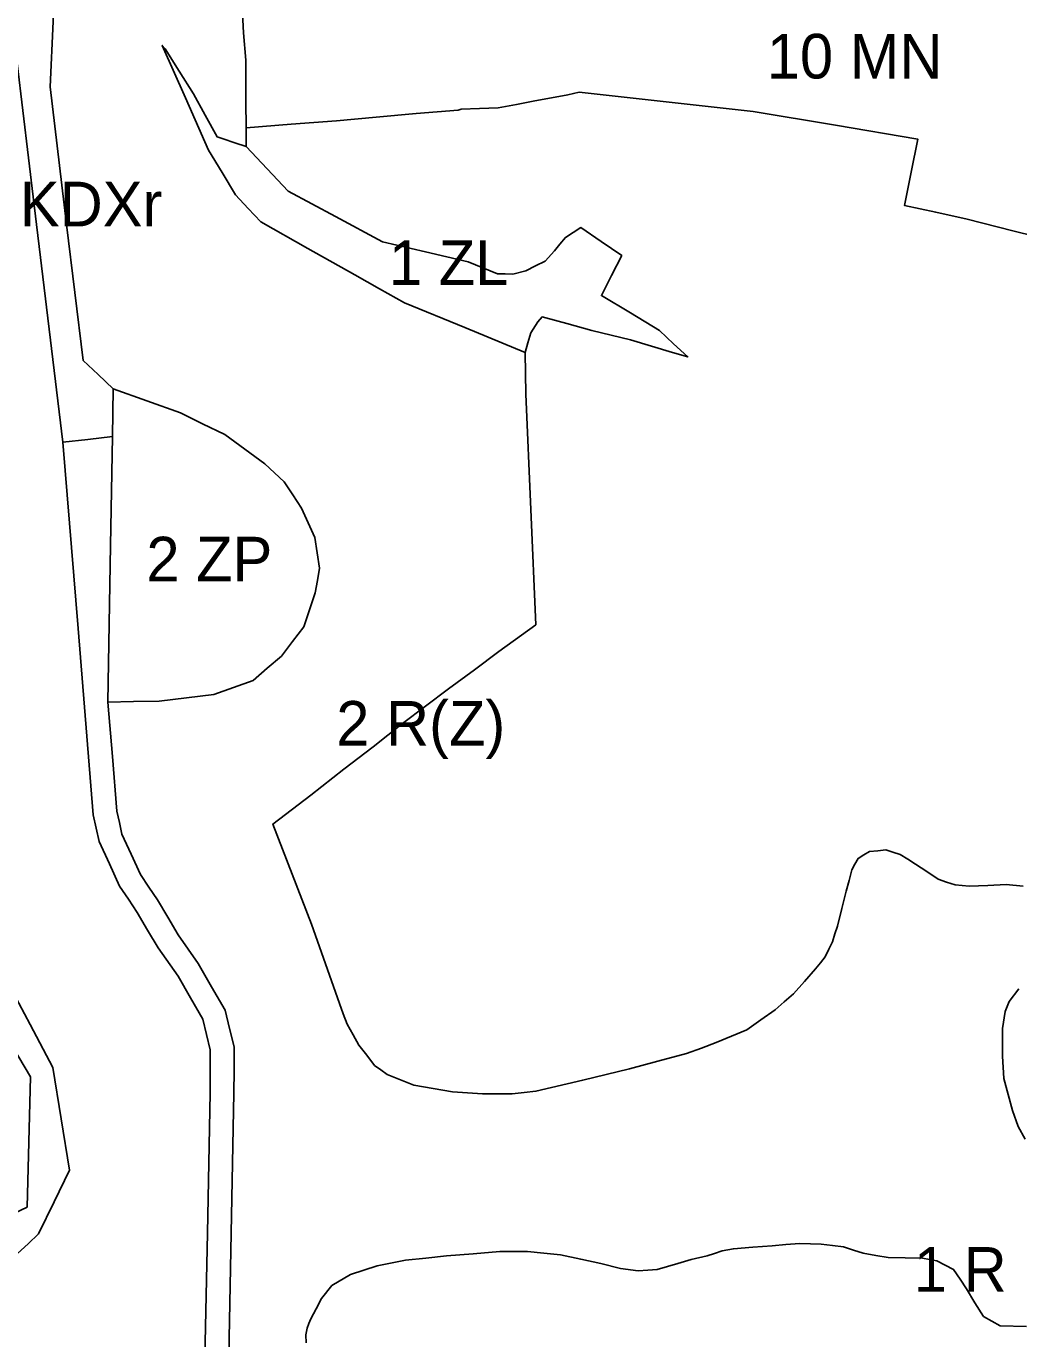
# Model space of a CAD drawing. Extents: x -295551 to -293631, y 22633 to 24461.
# Drawn here: x -294907.1 to -294573.4, y 23168.5 to 23609.6 of the extents above; entities that cross this region are included whole.
import ezdxf

# ---------------------------------------------------------------- set-up
doc = ezdxf.new("R2010")
doc.units = 0
doc.layers.add('linie_rozgraniczajace', color=7, linetype='Continuous')
doc.layers.add('oznaczenia_przeznaczen', color=7, linetype='Continuous')

msp = doc.modelspace()

# ---------------------------------------------------------------- linework, layer by layer
at = {"layer": 'linie_rozgraniczajace'}
for points in [[(-294833.26, 23584.36), (-294833.285, 23591.3), (-294833.31, 23598.24), (-294834, 23607.44), (-294834.32, 23611.79), (-294835.076, 23621.65), (-294835.832, 23631.51), (-294836.521, 23637.03), (-294837.21, 23642.55), (-294838.325, 23651.48), (-294839.44, 23660.41), (-294840.989, 23667.771)], [(-294914.016, 23629.187), (-294904.383, 23549.544), (-294894.749, 23469.901), (-294889.66, 23407.262), (-294884.572, 23344.624), (-294883.566, 23340.113), (-294882.561, 23335.602), (-294879.136, 23328.127), (-294875.71, 23320.651), (-294872.746, 23316.233), (-294869.781, 23311.815), (-294866.279, 23305.886), (-294862.778, 23299.956), (-294856.04, 23290.395), (-294851.888, 23283.151), (-294847.736, 23275.907), (-294846.469, 23270.782), (-294845.202, 23265.658), (-294845.232, 23258.409), (-294845.262, 23251.16), (-294846.188, 23203.99), (-294847.114, 23156.82)], [(-294899.096, 23589.295), (-294898.065, 23611.273)], [(-294834.32, 23611.79), (-294834, 23607.44), (-294833.31, 23598.24), (-294833.285, 23591.3), (-294833.26, 23584.36), (-294833.12, 23575.47), (-294833.15, 23569.21), (-294837, 23570.503), (-294840.849, 23571.796), (-294842.915, 23572.5), (-294846.898, 23579.745), (-294850.88, 23586.99), (-294855.658, 23594.502), (-294860.436, 23602.014), (-294861.352, 23603.227), (-294853.586, 23585.608), (-294845.82, 23567.99), (-294841.27, 23560.47), (-294836.72, 23552.95), (-294832.445, 23548.43), (-294828.17, 23543.91), (-294812.375, 23534.994), (-294796.58, 23526.077), (-294788.265, 23521.384), (-294779.95, 23516.69), (-294759.64, 23508.345), (-294739.33, 23500), (-294739.165, 23486.02), (-294737.448, 23447.26), (-294735.73, 23408.5), (-294740.576, 23404.966), (-294748.14, 23399.45), (-294756.39, 23393.32), (-294765.085, 23386.945), (-294780.59, 23375.36), (-294790.43, 23367.52), (-294800.26, 23359.99), (-294811.42, 23351.2), (-294824.153, 23341.524), (-294817.686, 23324.669), (-294811.218, 23307.814), (-294806.515, 23294.519), (-294801.812, 23281.223), (-294800.525, 23277.727), (-294799.238, 23274.231), (-294797.228, 23270.695), (-294795.217, 23267.159), (-294792.604, 23263.784), (-294789.99, 23260.408), (-294787.858, 23258.881), (-294785.727, 23257.354), (-294781.272, 23255.569), (-294776.817, 23253.784), (-294770.274, 23252.625), (-294763.731, 23251.466), (-294758.721, 23251.135), (-294753.711, 23250.804), (-294748.7, 23250.846), (-294743.69, 23250.887), (-294739.703, 23251.296), (-294735.717, 23251.704), (-294720.001, 23255.454), (-294704.284, 23259.203), (-294694.675, 23261.823), (-294685.067, 23264.444), (-294680.073, 23266.243), (-294675.079, 23268.042), (-294669.941, 23270.218), (-294664.803, 23272.395), (-294660.064, 23275.755), (-294655.324, 23279.114), (-294652.237, 23281.758), (-294649.15, 23284.402), (-294645.406, 23288.615), (-294641.662, 23292.829), (-294640.067, 23294.876), (-294638.471, 23296.923), (-294637.242, 23299.437), (-294636.013, 23301.951), (-294635.165, 23304.595), (-294634.317, 23307.239), (-294632.845, 23313.099), (-294631.373, 23318.959)], [(-294839.111, 23156.928), (-294838.187, 23203.997), (-294837.262, 23251.065), (-294837.23, 23258.84), (-294837.198, 23266.616), (-294838.718, 23272.765), (-294840.238, 23278.913), (-294844.762, 23286.806), (-294849.285, 23294.698), (-294852.669, 23299.5), (-294856.053, 23304.301), (-294859.531, 23310.191), (-294863.009, 23316.081), (-294865.858, 23320.326), (-294868.707, 23324.572), (-294871.822, 23331.369), (-294874.936, 23338.167), (-294875.79, 23341.995), (-294876.643, 23345.823), (-294878.133, 23364.17), (-294879.624, 23382.516), (-294871.006, 23382.646), (-294862.389, 23382.776), (-294853.199, 23383.905), (-294844.008, 23385.034), (-294837.382, 23387.419), (-294830.756, 23389.805), (-294826.039, 23393.865), (-294821.322, 23397.926), (-294817.546, 23402.874), (-294813.77, 23407.822), (-294811.845, 23413.517), (-294809.92, 23419.212), (-294809.187, 23423.373), (-294808.453, 23427.534), (-294809.27, 23432.687), (-294810.087, 23437.841), (-294812.297, 23442.757), (-294814.507, 23447.674), (-294817.417, 23452.106), (-294820.327, 23456.538), (-294826.928, 23462.541), (-294833.64, 23467.464), (-294840.352, 23472.386), (-294847.796, 23476.074), (-294855.241, 23479.762), (-294866.559, 23483.766), (-294877.877, 23487.769), (-294882.936, 23492.55), (-294887.994, 23497.331), (-294893.517, 23542.987), (-294899.096, 23589.295)], [(-294559.94, 23537.03), (-294575.31, 23540.915), (-294590.68, 23544.8), (-294601.256, 23547.111), (-294611.831, 23549.422), (-294609.576, 23560.586), (-294607.32, 23571.75), (-294635.005, 23576.375), (-294662.69, 23581), (-294691.91, 23584.275), (-294721.13, 23587.55), (-294725.01, 23586.62), (-294730.53, 23585.575), (-294736.05, 23584.53), (-294742.245, 23583.355), (-294748.44, 23582.18), (-294754.64, 23581.97), (-294760.84, 23581.76), (-294761.82, 23581.44), (-294768.93, 23580.9), (-294776.04, 23580.36), (-294789.43, 23579.13), (-294802.82, 23577.9), (-294817.97, 23576.685), (-294833.12, 23575.47), (-294833.26, 23584.36)], [(-294733.64, 23511.968), (-294732.371, 23511.622), (-294725.301, 23509.696), (-294716.963, 23507.423), (-294710.462, 23505.843), (-294703.962, 23504.262), (-294696.896, 23502.131), (-294689.83, 23500), (-294684.661, 23498.51), (-294689.44, 23502.965), (-294694.22, 23507.42), (-294703.96, 23513.28), (-294713.7, 23519.14), (-294710.29, 23525.855), (-294706.88, 23532.57), (-294713.74, 23537.285), (-294720.6, 23542), (-294723.215, 23540.345), (-294725.83, 23538.69), (-294727.63, 23536.43), (-294729.43, 23534.17), (-294732.64, 23530.7), (-294735.885, 23529.075), (-294739.13, 23527.45), (-294743.51, 23526.32), (-294746.05, 23526.39), (-294748.59, 23526.46), (-294753.535, 23528.44), (-294758.48, 23530.42), (-294772.88, 23533.81), (-294787.28, 23537.2), (-294803.13, 23545.73), (-294818.98, 23554.26), (-294826.065, 23561.735), (-294833.15, 23569.21), (-294833.12, 23575.47), (-294817.97, 23576.685), (-294802.82, 23577.9), (-294789.43, 23579.13), (-294776.04, 23580.36), (-294768.93, 23580.9), (-294761.82, 23581.44), (-294760.84, 23581.76), (-294754.64, 23581.97), (-294748.44, 23582.18), (-294742.245, 23583.355), (-294736.05, 23584.53), (-294730.53, 23585.575), (-294725.01, 23586.62), (-294721.13, 23587.55), (-294691.91, 23584.275), (-294662.69, 23581), (-294635.005, 23576.375), (-294607.32, 23571.75), (-294609.576, 23560.586), (-294611.831, 23549.422), (-294601.256, 23547.111), (-294590.68, 23544.8), (-294575.31, 23540.915), (-294559.94, 23537.03)], [(-294571.918, 23320.648), (-294577.553, 23321.14), (-294583.807, 23320.904), (-294590.061, 23320.668), (-294592.432, 23320.857), (-294594.803, 23321.045), (-294597.635, 23322.028), (-294600.467, 23323.011), (-294604.283, 23325.527), (-294608.099, 23328.042), (-294610.67, 23329.678), (-294613.24, 23331.314), (-294615.665, 23332.076), (-294618.091, 23332.838), (-294620.805, 23332.563), (-294623.52, 23332.288), (-294625.471, 23331.136), (-294627.421, 23329.983), (-294628.457, 23328.038), (-294629.492, 23326.094), (-294630.433, 23322.526), (-294631.373, 23318.959), (-294632.845, 23313.099), (-294634.317, 23307.239), (-294635.165, 23304.595), (-294636.013, 23301.951), (-294637.242, 23299.437), (-294638.471, 23296.923), (-294640.067, 23294.876), (-294641.662, 23292.829), (-294645.406, 23288.615), (-294649.15, 23284.402), (-294652.237, 23281.758), (-294655.324, 23279.114), (-294660.064, 23275.755), (-294664.803, 23272.395), (-294669.941, 23270.218), (-294675.079, 23268.042), (-294680.073, 23266.243), (-294685.067, 23264.444), (-294694.675, 23261.823), (-294704.284, 23259.203), (-294720.001, 23255.454), (-294735.717, 23251.704), (-294739.703, 23251.296), (-294743.69, 23250.887), (-294748.7, 23250.846), (-294753.711, 23250.804), (-294758.721, 23251.135), (-294763.731, 23251.466), (-294770.274, 23252.625), (-294776.817, 23253.784), (-294781.272, 23255.569), (-294785.727, 23257.354), (-294787.858, 23258.881), (-294789.99, 23260.408), (-294792.604, 23263.784), (-294795.217, 23267.159), (-294797.228, 23270.695), (-294799.238, 23274.231), (-294800.525, 23277.727), (-294801.812, 23281.223), (-294806.515, 23294.519), (-294811.218, 23307.814), (-294817.686, 23324.669), (-294824.153, 23341.524), (-294811.42, 23351.2), (-294800.26, 23359.99), (-294790.43, 23367.52), (-294780.59, 23375.36), (-294765.085, 23386.945), (-294756.39, 23393.32), (-294748.14, 23399.45), (-294740.576, 23404.966), (-294735.73, 23408.5), (-294737.448, 23447.26), (-294739.165, 23486.02), (-294739.33, 23500), (-294738.385, 23503.28), (-294737.44, 23506.56), (-294735.05, 23510.3), (-294733.64, 23511.968)], [(-294847.114, 23156.82), (-294846.188, 23203.99), (-294845.262, 23251.16), (-294845.232, 23258.409), (-294845.202, 23265.658), (-294846.469, 23270.782), (-294847.736, 23275.907), (-294851.888, 23283.151), (-294856.04, 23290.395), (-294862.778, 23299.956), (-294866.279, 23305.886), (-294869.781, 23311.815), (-294872.746, 23316.233), (-294875.71, 23320.651), (-294879.136, 23328.127), (-294882.561, 23335.602), (-294883.566, 23340.113), (-294884.572, 23344.624), (-294889.66, 23407.262), (-294894.749, 23469.901), (-294886.446, 23470.809), (-294878.144, 23471.716), (-294878.75, 23435.143), (-294879.624, 23382.516), (-294878.133, 23364.17), (-294876.643, 23345.823), (-294875.79, 23341.995), (-294874.936, 23338.167), (-294871.822, 23331.369), (-294868.707, 23324.572), (-294865.858, 23320.326), (-294863.009, 23316.081), (-294859.531, 23310.191), (-294856.053, 23304.301), (-294852.669, 23299.5), (-294849.285, 23294.698), (-294844.762, 23286.806), (-294840.238, 23278.913), (-294838.718, 23272.765), (-294837.198, 23266.616), (-294837.23, 23258.84), (-294837.262, 23251.065), (-294838.187, 23203.997), (-294839.111, 23156.928)], [(-294631.373, 23318.959), (-294630.433, 23322.526), (-294629.492, 23326.094), (-294628.457, 23328.038), (-294627.421, 23329.983), (-294625.471, 23331.136), (-294623.52, 23332.288), (-294620.805, 23332.563), (-294618.091, 23332.838), (-294615.665, 23332.076), (-294613.24, 23331.314), (-294610.67, 23329.678), (-294608.099, 23328.042), (-294604.283, 23325.527), (-294600.467, 23323.011), (-294597.635, 23322.028), (-294594.803, 23321.045), (-294592.432, 23320.857), (-294590.061, 23320.668), (-294583.807, 23320.904), (-294577.553, 23321.14), (-294571.918, 23320.648)], [(-294913.45, 23288.53), (-294905.78, 23274.125), (-294898.11, 23259.72), (-294895.33, 23242.46), (-294892.55, 23225.2), (-294897.765, 23214.5), (-294902.98, 23203.8), (-294906.49, 23200.48), (-294910, 23197.16)], [(-294910, 23197.16), (-294906.49, 23200.48), (-294902.98, 23203.8), (-294897.765, 23214.5), (-294892.55, 23225.2), (-294895.33, 23242.46), (-294898.11, 23259.72), (-294905.78, 23274.125), (-294913.45, 23288.53)], [(-294573.352, 23286.095), (-294576.599, 23281.855), (-294577.992, 23278.532), (-294578.887, 23272.813), (-294578.887, 23268.178), (-294578.887, 23263.543), (-294578.413, 23256.033), (-294576.919, 23250.638), (-294575.425, 23245.243), (-294573.547, 23239.861), (-294571.176, 23235.548)], [(-294577.992, 23278.532), (-294576.599, 23281.855), (-294573.352, 23286.095)], [(-294571.176, 23235.548), (-294573.547, 23239.861), (-294575.425, 23245.243), (-294576.919, 23250.638), (-294578.413, 23256.033), (-294578.887, 23263.543), (-294578.887, 23268.178), (-294578.887, 23272.813), (-294577.992, 23278.532)], [(-294931.45, 23201.07), (-294906.826, 23212.799), (-294905.654, 23256.518), (-294913.861, 23270.38)], [(-294812.975, 23167.207), (-294813.115, 23169.882), (-294812.667, 23172.127), (-294812.047, 23173.676), (-294811.427, 23175.225), (-294809.629, 23178.633), (-294807.831, 23182.042), (-294804.292, 23186.457), (-294798.018, 23190.121), (-294793.541, 23191.565), (-294789.065, 23193.01), (-294779.548, 23194.912), (-294772.688, 23195.647), (-294765.828, 23196.382), (-294756.86, 23197.104), (-294747.892, 23197.826), (-294743.242, 23197.851), (-294738.592, 23197.875), (-294733.017, 23197.291), (-294727.443, 23196.707), (-294720.65, 23195.247), (-294713.858, 23193.788), (-294707.249, 23192.089), (-294701.324, 23191.375), (-294698.116, 23191.569), (-294694.908, 23191.764), (-294691.477, 23192.777), (-294688.047, 23193.791), (-294683.503, 23195.184), (-294678.134, 23196.371), (-294675.63, 23197.196), (-294673.126, 23198.022), (-294671.21, 23198.403), (-294669.295, 23198.784), (-294662.791, 23199.289), (-294656.286, 23199.794), (-294651.661, 23200.167), (-294647.036, 23200.54), (-294643.41, 23200.412), (-294639.784, 23200.283), (-294636.025, 23199.834), (-294632.267, 23199.386), (-294628.954, 23198.318), (-294625.642, 23197.25), (-294621.474, 23196.545), (-294617.306, 23195.839), (-294611.521, 23195.742), (-294605.736, 23195.645), (-294603.341, 23195.157), (-294600.945, 23194.668), (-294598.109, 23193.252), (-294595.273, 23191.835), (-294593.124, 23188.544), (-294590.974, 23185.254), (-294588.086, 23180.646), (-294585.199, 23176.039), (-294579.66, 23172.908), (-294570.733, 23172.653)], [(-294570.733, 23172.653), (-294579.66, 23172.908), (-294585.199, 23176.039), (-294588.086, 23180.646), (-294590.974, 23185.254), (-294593.124, 23188.544), (-294595.273, 23191.835), (-294598.109, 23193.252), (-294600.945, 23194.668), (-294603.341, 23195.157), (-294605.736, 23195.645), (-294611.521, 23195.742), (-294617.306, 23195.839), (-294621.474, 23196.545), (-294625.642, 23197.25), (-294628.954, 23198.318), (-294632.267, 23199.386), (-294636.025, 23199.834), (-294639.784, 23200.283), (-294643.41, 23200.412), (-294647.036, 23200.54), (-294651.661, 23200.167), (-294656.286, 23199.794), (-294662.791, 23199.289), (-294669.295, 23198.784), (-294671.21, 23198.403), (-294673.126, 23198.022), (-294675.63, 23197.196), (-294678.134, 23196.371), (-294683.503, 23195.184), (-294688.047, 23193.791), (-294691.477, 23192.777), (-294694.908, 23191.764)], [(-294694.908, 23191.764), (-294698.116, 23191.569), (-294701.324, 23191.375), (-294707.249, 23192.089), (-294713.858, 23193.788), (-294720.65, 23195.247), (-294727.443, 23196.707), (-294733.017, 23197.291), (-294738.592, 23197.875), (-294743.242, 23197.851), (-294747.892, 23197.826), (-294756.86, 23197.104), (-294765.828, 23196.382), (-294772.688, 23195.647), (-294779.548, 23194.912), (-294789.065, 23193.01), (-294793.541, 23191.565), (-294798.018, 23190.121), (-294804.292, 23186.457), (-294807.831, 23182.042), (-294809.629, 23178.633), (-294811.427, 23175.225), (-294812.047, 23173.676), (-294812.667, 23172.127), (-294813.115, 23169.882), (-294812.975, 23167.207)]]:
    msp.add_lwpolyline(points, dxfattribs=at)
for points in [[(-294914.016, 23629.187), (-294905.525, 23631.219), (-294897.034, 23633.251), (-294898.065, 23611.273), (-294899.096, 23589.295), (-294893.517, 23542.987), (-294887.994, 23497.331), (-294882.936, 23492.55), (-294877.877, 23487.769), (-294878.144, 23471.716), (-294886.446, 23470.809), (-294894.749, 23469.901), (-294904.383, 23549.544)], [(-294861.352, 23603.227), (-294860.436, 23602.014), (-294855.658, 23594.502), (-294850.88, 23586.99), (-294846.898, 23579.745), (-294842.915, 23572.5), (-294840.849, 23571.796), (-294837, 23570.503), (-294833.15, 23569.21), (-294826.065, 23561.735), (-294818.98, 23554.26), (-294803.13, 23545.73), (-294787.28, 23537.2), (-294772.88, 23533.81), (-294758.48, 23530.42), (-294753.535, 23528.44), (-294748.59, 23526.46), (-294746.05, 23526.39), (-294743.51, 23526.32), (-294739.13, 23527.45), (-294735.885, 23529.075), (-294732.64, 23530.7), (-294729.43, 23534.17), (-294727.63, 23536.43), (-294725.83, 23538.69), (-294723.215, 23540.345), (-294720.6, 23542), (-294713.74, 23537.285), (-294706.88, 23532.57), (-294710.29, 23525.855), (-294713.7, 23519.14), (-294703.96, 23513.28), (-294694.22, 23507.42), (-294689.44, 23502.965), (-294684.661, 23498.51), (-294689.83, 23500), (-294696.896, 23502.131), (-294703.962, 23504.262), (-294710.462, 23505.843), (-294716.963, 23507.423), (-294725.301, 23509.696), (-294732.371, 23511.622), (-294733.64, 23511.968), (-294735.05, 23510.3), (-294737.44, 23506.56), (-294738.385, 23503.28), (-294739.33, 23500), (-294759.64, 23508.345), (-294779.95, 23516.69), (-294788.265, 23521.384), (-294796.58, 23526.077), (-294812.375, 23534.994), (-294828.17, 23543.91), (-294832.445, 23548.43), (-294836.72, 23552.95), (-294841.27, 23560.47), (-294845.82, 23567.99), (-294853.586, 23585.608)], [(-294879.624, 23382.516), (-294878.75, 23435.143), (-294878.144, 23471.716), (-294877.877, 23487.769), (-294866.559, 23483.766), (-294855.241, 23479.762), (-294847.796, 23476.074), (-294840.352, 23472.386), (-294833.64, 23467.464), (-294826.928, 23462.541), (-294820.327, 23456.538), (-294817.417, 23452.106), (-294814.507, 23447.674), (-294812.297, 23442.757), (-294810.087, 23437.841), (-294809.27, 23432.687), (-294808.453, 23427.534), (-294809.187, 23423.373), (-294809.92, 23419.212), (-294811.845, 23413.517), (-294813.77, 23407.822), (-294817.546, 23402.874), (-294821.322, 23397.926), (-294826.039, 23393.865), (-294830.756, 23389.805), (-294837.382, 23387.419), (-294844.008, 23385.034), (-294853.199, 23383.905), (-294862.389, 23382.776), (-294871.006, 23382.646)]]:
    msp.add_lwpolyline(points, close=True, dxfattribs=at)

# ---------------------------------------------------------------- texts
at = {"layer": 'oznaczenia_przeznaczen'}
for s, p in [('10 MN', (-294658.097, 23592.087)), ('2 KDXr', (-294925.976, 23542.388)), ('1 ZL', (-294785.155, 23522.711)), ('2 ZP', (-294866.701, 23423.064)), ('2 R(Z)', (-294802.861, 23367.86)), ('1 R', (-294608.635, 23184.335))]:
    msp.add_text(s, height=15, dxfattribs=at).set_placement(p)

doc.saveas('drawing.dxf')
